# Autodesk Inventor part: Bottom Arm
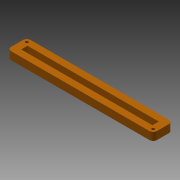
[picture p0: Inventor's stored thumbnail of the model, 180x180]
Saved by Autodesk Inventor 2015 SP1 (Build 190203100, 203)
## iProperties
Created: 2008-11
Part Number: Bottom Arm
Document SubType Name: Modeling
Designer: dwoollam
Density: 7.85 g/cm^3
Material: Steel
Appearance: Orange
Mass: 1.05318e+06 g
Surface Area: 37103.5 cm^2
Volume: 134163 cm^3
Dwg_Category: Clearance_Mewp
INSTALLATION: False
CIVIL_WORK: False
EARTHING: False
MOUNTING: False
Author: dwoollam
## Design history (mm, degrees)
sketch "Sketch1"
  geometry: L1 (-1425, 200)-(1425, 200); L2 (1500, 125)-(1500, -125); L3 (1425, -200)-(-1425, -200); L4 (-1500, -125)-(-1500, 125); L5 (-1350, 65)-(1350, 65); L6 (1350, 65)-(1350, -65); L7 (1350, -65)-(-1350, -65); L8 (-1350, -65)-(-1350, 65); C1 r 30 at (-1425, 125); C2 r 30 at (1425, -125); A1 r 75 centre (-1425, 125) between (-1425, 200) and (-1500, 125); A2 r 75 centre (-1425, -125) between (-1500, -125) and (-1425, -200); A3 r 75 centre (1425, -125) between (1425, -200) and (1500, -125); A4 r 75 centre (1425, 125) between (1500, 125) and (1425, 200); 3 further points
  constraints: 16 end point, 8 point on circle, 8 tangent, 6 centre point, 4 equal radius, 4 parallel, 2 horizontal, 2 midpoint, 2 perpendicular, 1 horizontal alignment, 1 vertical alignment
  dimensions: "d2" = 75 radius of A1; "d3" = 400 distance between parallel lines of L1 L3; "d4" = 3000 distance between parallel lines of L2 L4; "d5" = 150 distance between parallel lines of L4 L8; "d6" = 150 distance between parallel lines of L2 L6 (= d5); "d7" = 135 distance between parallel lines of L1 L5; "d8" = 135 distance between parallel lines of L3 L7 (= d7); "d9" = 75 distance from line of L1 C1.centre (= d2); "d10" = 75 distance from line of L4 C1.centre (= d9); "d11" = 60 diameter of C1; "d12" = 75 distance from line of L2 C2.centre (= d9); "d13" = 75 distance from line of L3 C2.centre (= d12)
extrude "Extrusion1" new body sketch "Sketch1" stored distance "d14" = 160; taper "d15" = 0 deg
body "Solid1"
